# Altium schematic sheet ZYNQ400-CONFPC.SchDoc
size A3
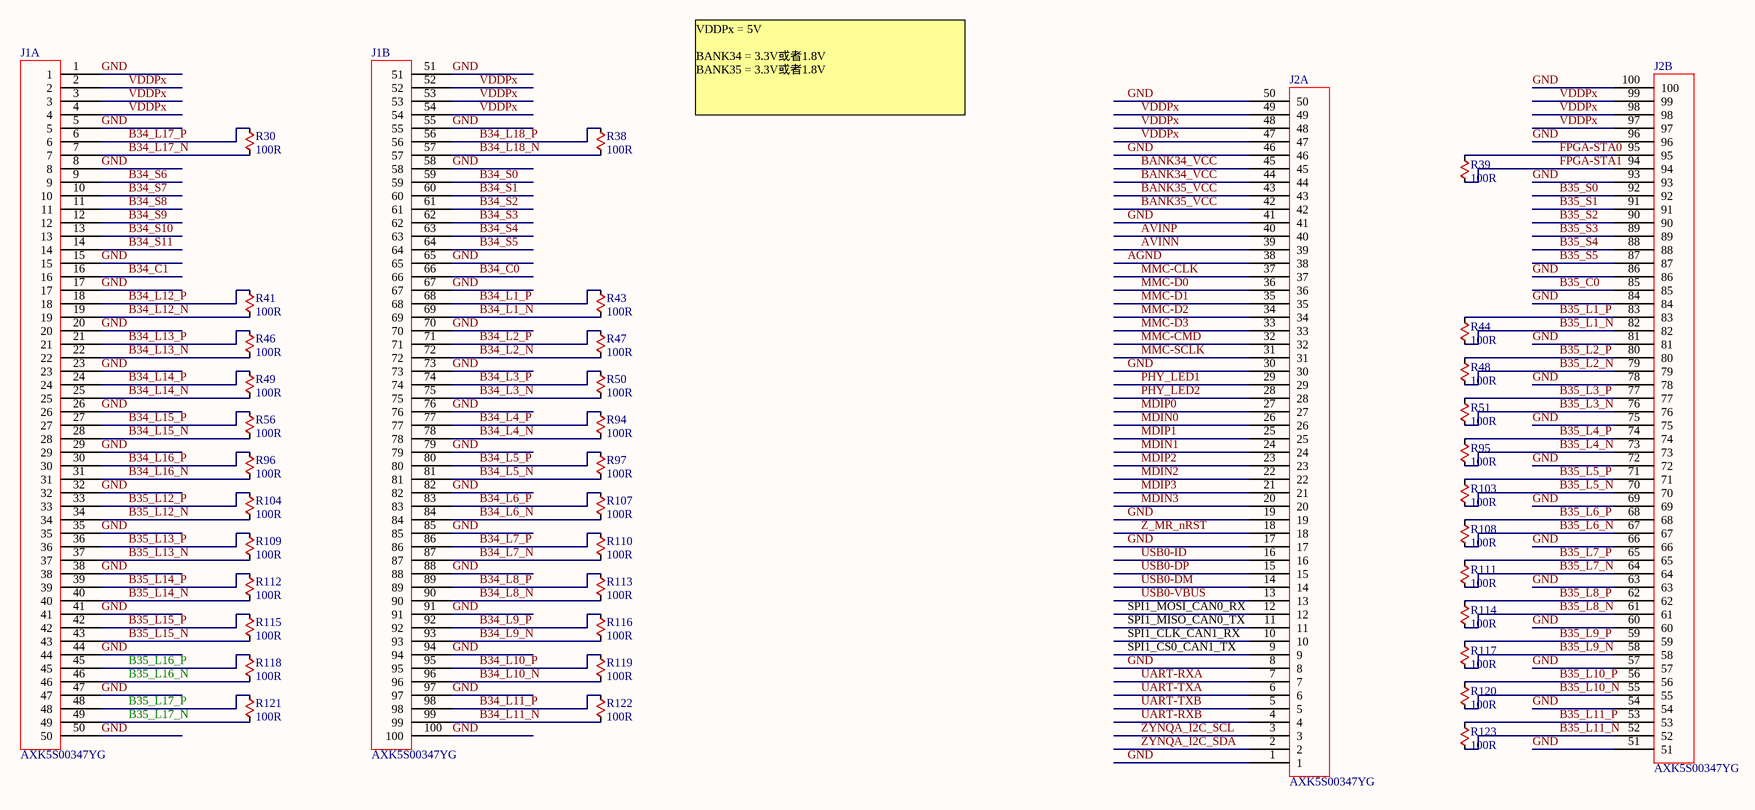
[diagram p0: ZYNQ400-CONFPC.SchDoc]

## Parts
J1  AXK5S00347YG  [AXK5S00347YG]  (parts A,B of 2)
J2  AXK5S00347YG  [AXK5S00347YG]  (parts A,B of 2)
R30  100R  [0201]
R38  100R  [0201]
R39  100R  [0201]
R41  100R  [0201]
R43  100R  [0201]
R44  100R  [0201]
R46  100R  [0201]
R47  100R  [0201]
R48  100R  [0201]
R49  100R  [0201]
R50  100R  [0201]
R51  100R  [0201]
R56  100R  [0201]
R94  100R  [0201]
R95  100R  [0201]
R96  100R  [0201]
R97  100R  [0201]
R103  100R  [0201]
R104  100R  [0201]
R107  100R  [0201]
R108  100R  [0201]
R109  100R  [0201]
R110  100R  [0201]
R111  100R  [0201]
R112  100R  [0201]
R113  100R  [0201]
R114  100R  [0201]
R115  100R  [0201]
R116  100R  [0201]
R117  100R  [0201]
R118  100R  [0201]
R119  100R  [0201]
R120  100R  [0201]
R121  100R  [0201]
R122  100R  [0201]
R123  100R  [0201]

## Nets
AGND: J2.38
AVINN: J2.39
AVINP: J2.40
B34_C0: J1.66
B34_C1: J1.16
B34_L1_N: J1.69 R43.2
B34_L1_P: J1.68 R43.1
B34_L2_N: J1.72 R47.2
B34_L2_P: J1.71 R47.1
B34_L3_N: J1.75 R50.2
B34_L3_P: J1.74 R50.1
B34_L4_N: J1.78 R94.2
B34_L4_P: J1.77 R94.1
B34_L5_N: J1.81 R97.2
B34_L5_P: J1.80 R97.1
B34_L6_N: J1.84 R107.2
B34_L6_P: J1.83 R107.1
B34_L7_N: J1.87 R110.2
B34_L7_P: J1.86 R110.1
B34_L8_N: J1.90 R113.2
B34_L8_P: J1.89 R113.1
B34_L9_N: J1.93 R116.2
B34_L9_P: J1.92 R116.1
B34_L10_N: J1.96 R119.2
B34_L10_P: J1.95 R119.1
B34_L11_N: J1.99 R122.2
B34_L11_P: J1.98 R122.1
B34_L12_N: J1.19 R41.2
B34_L12_P: J1.18 R41.1
B34_L13_N: J1.22 R46.2
B34_L13_P: J1.21 R46.1
B34_L14_N: J1.25 R49.2
B34_L14_P: J1.24 R49.1
B34_L15_N: J1.28 R56.2
B34_L15_P: J1.27 R56.1
B34_L16_N: J1.31 R96.2
B34_L16_P: J1.30 R96.1
B34_L17_N: J1.7 R30.2
B34_L17_P: J1.6 R30.1
B34_L18_N: J1.57 R38.2
B34_L18_P: J1.56 R38.1
B34_S0: J1.59
B34_S1: J1.60
B34_S2: J1.61
B34_S3: J1.62
B34_S4: J1.63
B34_S5: J1.64
B34_S6: J1.9
B34_S7: J1.10
B34_S8: J1.11
B34_S9: J1.12
B34_S10: J1.13
B34_S11: J1.14
B35_C0: J2.85
B35_L1_N: J2.82 R44.1
B35_L1_P: J2.83 R44.2
B35_L2_N: J2.79 R48.1
B35_L2_P: J2.80 R48.2
B35_L3_N: J2.76 R51.1
B35_L3_P: J2.77 R51.2
B35_L4_N: J2.73 R95.1
B35_L4_P: J2.74 R95.2
B35_L5_N: J2.70 R103.1
B35_L5_P: J2.71 R103.2
B35_L6_N: J2.67 R108.1
B35_L6_P: J2.68 R108.2
B35_L7_N: J2.64 R111.1
B35_L7_P: J2.65 R111.2
B35_L8_N: J2.61 R114.1
B35_L8_P: J2.62 R114.2
B35_L9_N: J2.58 R117.1
B35_L9_P: J2.59 R117.2
B35_L10_N: J2.55 R120.1
B35_L10_P: J2.56 R120.2
B35_L11_N: J2.52 R123.1
B35_L11_P: J2.53 R123.2
B35_L12_N: J1.34 R104.2
B35_L12_P: J1.33 R104.1
B35_L13_N: J1.37 R109.2
B35_L13_P: J1.36 R109.1
B35_L14_N: J1.40 R112.2
B35_L14_P: J1.39 R112.1
B35_L15_N: J1.43 R115.2
B35_L15_P: J1.42 R115.1
B35_L16_N: J1.46 R118.2
B35_L16_P: J1.45 R118.1
B35_L17_N: J1.49 R121.2
B35_L17_P: J1.48 R121.1
B35_S0: J2.92
B35_S1: J2.91
B35_S2: J2.90
B35_S3: J2.89
B35_S4: J2.88
B35_S5: J2.87
BANK34_VCC: J2.44 J2.45
BANK35_VCC: J2.42 J2.43
FPGA-STA0: J2.95 R39.2
FPGA-STA1: J2.94 R39.1
GND: J1.1 J1.5 J1.8 J1.15 J1.17 J1.20 J1.23 J1.26 J1.29 J1.32 J1.35 J1.38 J1.41 J1.44 J1.47 J1.50 J1.51 J1.55 J1.58 J1.65 J1.67 J1.70 J1.73 J1.76 J1.79 J1.82 J1.85 J1.88 J1.91 J1.94 J1.97 J1.100 J2.1 J2.8 J2.17 J2.19 J2.30 J2.41 J2.46 J2.50 J2.51 J2.54 J2.57 J2.60 J2.63 J2.66 J2.69 J2.72 J2.75 J2.78 J2.81 J2.84 J2.86 J2.93 J2.96 J2.100
MDIN0: J2.26
MDIN1: J2.24
MDIN2: J2.22
MDIN3: J2.20
MDIP0: J2.27
MDIP1: J2.25
MDIP2: J2.23
MDIP3: J2.21
MMC-CLK: J2.37
MMC-CMD: J2.32
MMC-D0: J2.36
MMC-D1: J2.35
MMC-D2: J2.34
MMC-D3: J2.33
MMC-SCLK: J2.31
PHY_LED1: J2.29
PHY_LED2: J2.28
SPI1_CLK_CAN1_RX: J2.10
SPI1_CS0_CAN1_TX: J2.9
SPI1_MISO_CAN0_TX: J2.11
SPI1_MOSI_CAN0_RX: J2.12
UART-RXA: J2.7
UART-RXB: J2.4
UART-TXA: J2.6
UART-TXB: J2.5
USB0-DM: J2.14
USB0-DP: J2.15
USB0-ID: J2.16
USB0-VBUS: J2.13
VDDPx: J1.2 J1.3 J1.4 J1.52 J1.53 J1.54 J2.47 J2.48 J2.49 J2.97 J2.98 J2.99
Z_MR_nRST: J2.18
ZYNQA_I2C_SCL: J2.3
ZYNQA_I2C_SDA: J2.2

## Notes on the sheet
- VDDPx = 5V
  BANK34 = 3.3V或者1.8V
  BANK35 = 3.3V或者1.8V

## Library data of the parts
J2 = AXK6S00647YG
R30 R38 R39 R41 R43 R44 R46-R51 R56 R94-R97 R103 R104 R107-R123 = RESISTOR: Generic Resistor; Value: 40.2R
